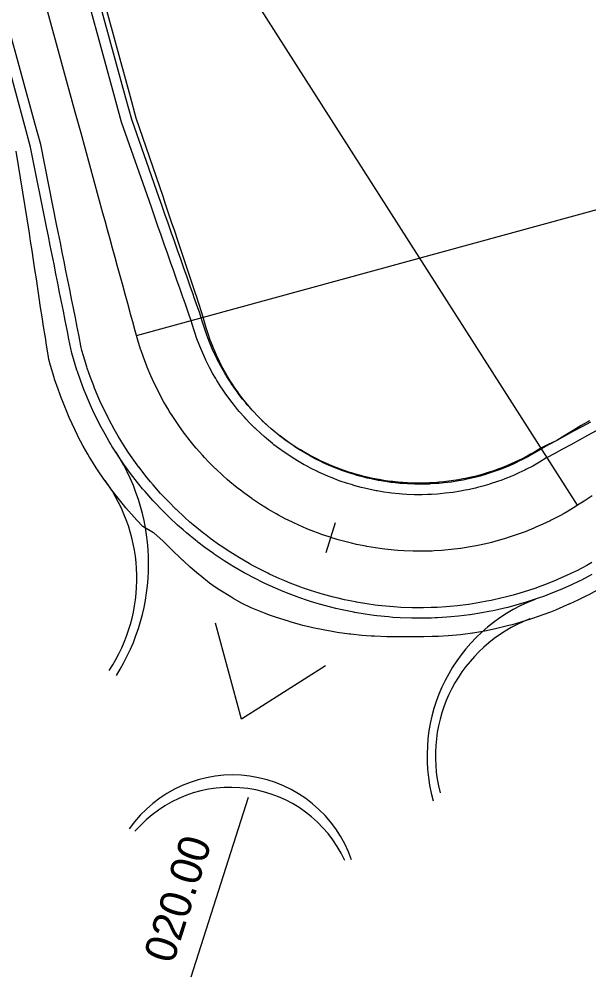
# Model space of a CAD drawing. Extents: x -550605 to -538780, y -1102367 to -1093705.
# Drawn here: x -547316.42 to -547289.25, y -1101242.46 to -1101196.75 of the extents above; entities that cross this region are included whole.
import ezdxf

# ---------------------------------------------------------------- set-up
doc = ezdxf.new("R2010")
doc.units = 0
for name, color, linetype in [('SIT - horní hrana zářezu', 7, 'Continuous'), ('SIT - hrany vozovky', 7, 'Continuous'), ('SIT - oblouky - hrany', 7, 'Continuous'), ('SIT - oblouky - koruna', 7, 'Continuous'), ('SIT - osa cesty', 7, 'Continuous'), ('SIT - paty násypů', 7, 'Continuous'), ('SIT - poloměry oblouků', 7, 'Continuous'), ('SIT - staničení hlavních bodů', 7, 'Continuous'), ('SIT - staničení po 30m', 7, 'Continuous')]:
    doc.layers.add(name, color=color, linetype=linetype)

msp = doc.modelspace()

# ---------------------------------------------------------------- linework, layer by layer
at = {"layer": 'SIT - horní hrana zářezu'}
msp.add_lwpolyline([(-547290.779, -1101216.854), (-547291.19, -1101217.054), (-547291.534, -1101217.223), (-547291.582, -1101217.253), (-547291.881, -1101217.432), (-547292.029, -1101217.516), (-547292.186, -1101217.602), (-547292.496, -1101217.762), (-547292.538, -1101217.783), (-547292.811, -1101217.913), (-547293.061, -1101218.023), (-547293.064, -1101218.024), (-547293.131, -1101218.053), (-547293.455, -1101218.182), (-547293.595, -1101218.235), (-547293.783, -1101218.301), (-547294.114, -1101218.41), (-547294.14, -1101218.418), (-547294.449, -1101218.508), (-547294.693, -1101218.572), (-547294.787, -1101218.595), (-547295.127, -1101218.671), (-547295.254, -1101218.697), (-547295.469, -1101218.736), (-547295.814, -1101218.791), (-547295.821, -1101218.792), (-547296.16, -1101218.834), (-547296.392, -1101218.857), (-547296.507, -1101218.866), (-547296.785, -1101218.884), (-547296.855, -1101218.887), (-547296.965, -1101218.891), (-547297.204, -1101218.897), (-547297.54, -1101218.896), (-547297.553, -1101218.896), (-547297.901, -1101218.883), (-547298.114, -1101218.87), (-547298.249, -1101218.86), (-547298.596, -1101218.825), (-547298.686, -1101218.814), (-547298.942, -1101218.779), (-547299.255, -1101218.728), (-547299.287, -1101218.722), (-547299.629, -1101218.655), (-547299.818, -1101218.612), (-547299.969, -1101218.576), (-547300.306, -1101218.486), (-547300.374, -1101218.467), (-547300.576, -1101218.406), (-547300.641, -1101218.386), (-547300.923, -1101218.292), (-547300.972, -1101218.275), (-547301.299, -1101218.153), (-547301.461, -1101218.089), (-547301.623, -1101218.021), (-547301.942, -1101217.879), (-547301.988, -1101217.858), (-547302.257, -1101217.727), (-547302.503, -1101217.599), (-547302.566, -1101217.564), (-547302.871, -1101217.392), (-547303.003, -1101217.313), (-547303.17, -1101217.21), (-547303.463, -1101217.019), (-547303.488, -1101217.001), (-547303.749, -1101216.816), (-547303.955, -1101216.661), (-547303.976, -1101216.645), (-547304.028, -1101216.605), (-547304.3, -1101216.384), (-547304.403, -1101216.297), (-547304.565, -1101216.156)], dxfattribs=at)
at = {"layer": 'SIT - hrany vozovky'}
for points in [[(-547288.909, -1101216.407), (-547289.309, -1101216.625), (-547289.709, -1101216.842), (-547290.109, -1101217.06), (-547290.509, -1101217.277), (-547290.909, -1101217.494), (-547291.245, -1101217.677), (-547291.295, -1101217.708), (-547291.608, -1101217.899), (-547291.763, -1101217.988), (-547291.927, -1101218.079), (-547292.252, -1101218.249), (-547292.296, -1101218.271), (-547292.583, -1101218.408), (-547292.844, -1101218.524), (-547292.848, -1101218.526), (-547292.918, -1101218.556), (-547293.258, -1101218.693), (-547293.405, -1101218.749), (-547293.602, -1101218.819), (-547293.95, -1101218.934), (-547293.977, -1101218.943), (-547294.302, -1101219.038), (-547294.559, -1101219.106), (-547294.657, -1101219.13), (-547295.014, -1101219.211), (-547295.148, -1101219.238), (-547295.375, -1101219.28), (-547295.737, -1101219.337), (-547295.744, -1101219.338), (-547296.1, -1101219.382), (-547296.344, -1101219.406), (-547296.466, -1101219.416), (-547296.758, -1101219.434), (-547296.831, -1101219.438), (-547296.947, -1101219.442), (-547297.198, -1101219.448), (-547297.551, -1101219.446), (-547297.565, -1101219.446), (-547297.931, -1101219.432), (-547298.155, -1101219.417), (-547298.297, -1101219.406), (-547298.661, -1101219.368), (-547298.756, -1101219.357), (-547299.025, -1101219.319), (-547299.353, -1101219.264), (-547299.386, -1101219.258), (-547299.745, -1101219.185), (-547299.944, -1101219.139), (-547300.102, -1101219.1), (-547300.456, -1101219.004), (-547300.527, -1101218.983), (-547300.739, -1101218.919), (-547300.807, -1101218.897), (-547301.102, -1101218.797), (-547301.153, -1101218.778), (-547301.496, -1101218.648), (-547301.665, -1101218.579), (-547301.835, -1101218.507), (-547302.168, -1101218.355), (-547302.216, -1101218.332), (-547302.497, -1101218.192), (-547302.754, -1101218.056), (-547302.82, -1101218.019), (-547303.137, -1101217.836), (-547303.275, -1101217.751), (-547303.448, -1101217.642), (-547303.753, -1101217.438), (-547303.78, -1101217.419), (-547304.051, -1101217.224), (-547304.266, -1101217.061), (-547304.288, -1101217.044), (-547304.342, -1101217.001), (-547304.626, -1101216.769), (-547304.733, -1101216.677), (-547304.901, -1101216.527), (-547305.169, -1101216.277), (-547305.178, -1101216.269), (-547305.429, -1101216.018), (-547305.6, -1101215.837), (-547305.68, -1101215.751), (-547305.922, -1101215.475), (-547305.999, -1101215.384), (-547306.155, -1101215.193), (-547306.374, -1101214.909), (-547306.379, -1101214.902), (-547306.593, -1101214.605), (-547306.722, -1101214.416), (-547306.798, -1101214.3), (-547306.958, -1101214.046), (-547306.993, -1101213.99), (-547307.044, -1101213.904), (-547307.177, -1101213.673), (-547307.337, -1101213.377), (-547307.351, -1101213.35), (-547307.514, -1101213.022), (-547307.602, -1101212.834), (-547307.667, -1101212.689), (-547307.809, -1101212.351), (-547307.838, -1101212.278), (-547307.94, -1101212.008), (-547308.044, -1101211.71), (-547308.059, -1101211.662), (-547308.168, -1101211.311), (-547308.219, -1101211.131), (-547308.292, -1101210.921), (-547308.443, -1101210.491), (-547308.568, -1101210.135), (-547308.594, -1101210.061), (-547308.744, -1101209.632), (-547308.895, -1101209.202), (-547309.045, -1101208.772), (-547309.196, -1101208.342), (-547309.347, -1101207.913), (-547309.497, -1101207.483), (-547309.648, -1101207.053), (-547309.798, -1101206.623), (-547309.949, -1101206.194), (-547310.099, -1101205.764), (-547310.225, -1101205.405), (-547311.534, -1101201.671), (-547311.812, -1101200.656), (-547313.118, -1101195.884)], [(-547289.177, -1101215.986), (-547289.578, -1101216.203), (-547289.978, -1101216.421), (-547290.378, -1101216.638), (-547290.778, -1101216.855), (-547291.178, -1101217.073), (-547291.513, -1101217.255), (-547291.561, -1101217.285), (-547291.861, -1101217.467), (-547292.008, -1101217.552), (-547292.166, -1101217.639), (-547292.477, -1101217.802), (-547292.519, -1101217.823), (-547292.792, -1101217.954), (-547293.042, -1101218.065), (-547293.045, -1101218.067), (-547293.113, -1101218.095), (-547293.438, -1101218.227), (-547293.578, -1101218.28), (-547293.767, -1101218.347), (-547294.099, -1101218.457), (-547294.125, -1101218.465), (-547294.435, -1101218.556), (-547294.681, -1101218.621), (-547294.775, -1101218.644), (-547295.116, -1101218.721), (-547295.244, -1101218.747), (-547295.461, -1101218.787), (-547295.807, -1101218.842), (-547295.814, -1101218.843), (-547296.154, -1101218.885), (-547296.387, -1101218.908), (-547296.503, -1101218.917), (-547296.783, -1101218.935), (-547296.853, -1101218.938), (-547296.964, -1101218.943), (-547297.203, -1101218.948), (-547297.541, -1101218.946), (-547297.554, -1101218.946), (-547297.904, -1101218.933), (-547298.118, -1101218.919), (-547298.253, -1101218.908), (-547298.602, -1101218.872), (-547298.692, -1101218.861), (-547298.949, -1101218.825), (-547299.263, -1101218.772), (-547299.295, -1101218.766), (-547299.638, -1101218.697), (-547299.828, -1101218.653), (-547299.979, -1101218.616), (-547300.317, -1101218.524), (-547300.385, -1101218.504), (-547300.587, -1101218.442), (-547300.652, -1101218.421), (-547300.934, -1101218.325), (-547300.984, -1101218.308), (-547301.311, -1101218.184), (-547301.473, -1101218.118), (-547301.635, -1101218.049), (-547301.954, -1101217.904), (-547302, -1101217.882), (-547302.268, -1101217.748), (-547302.513, -1101217.618), (-547302.577, -1101217.582), (-547302.88, -1101217.407), (-547303.012, -1101217.326), (-547303.177, -1101217.222), (-547303.469, -1101217.027), (-547303.494, -1101217.009), (-547303.753, -1101216.823), (-547303.959, -1101216.667), (-547303.98, -1101216.65), (-547304.031, -1101216.609), (-547304.302, -1101216.387), (-547304.405, -1101216.3), (-547304.566, -1101216.156), (-547304.822, -1101215.917), (-547304.83, -1101215.909), (-547305.07, -1101215.67), (-547305.234, -1101215.497), (-547305.31, -1101215.414), (-547305.541, -1101215.151), (-547305.615, -1101215.063), (-547305.764, -1101214.881), (-547305.973, -1101214.61), (-547305.978, -1101214.603), (-547306.183, -1101214.319), (-547306.306, -1101214.139), (-547306.379, -1101214.028), (-547306.532, -1101213.785), (-547306.565, -1101213.731), (-547306.613, -1101213.65), (-547306.741, -1101213.428), (-547306.894, -1101213.145), (-547306.907, -1101213.12), (-547307.063, -1101212.806), (-547307.147, -1101212.626), (-547307.209, -1101212.488), (-547307.345, -1101212.165), (-547307.373, -1101212.095), (-547307.47, -1101211.837), (-547307.569, -1101211.552), (-547307.584, -1101211.506), (-547307.688, -1101211.171), (-547307.736, -1101210.999), (-547307.81, -1101210.789), (-547307.961, -1101210.359), (-547308.085, -1101210.003), (-547308.111, -1101209.929), (-547308.262, -1101209.5), (-547308.412, -1101209.07), (-547308.563, -1101208.64), (-547308.714, -1101208.21), (-547308.864, -1101207.781), (-547309.015, -1101207.351), (-547309.165, -1101206.921), (-547309.316, -1101206.491), (-547309.467, -1101206.062), (-547309.617, -1101205.632), (-547309.743, -1101205.273), (-547311.051, -1101201.539), (-547311.329, -1101200.524), (-547312.635, -1101195.752)], [(-547289.107, -1101222.69), (-547289.351, -1101222.824), (-547289.831, -1101223.075), (-547289.896, -1101223.108), (-547290.319, -1101223.31), (-547290.706, -1101223.483), (-547290.711, -1101223.485), (-547290.815, -1101223.529), (-547291.317, -1101223.732), (-547291.535, -1101223.814), (-547291.826, -1101223.919), (-547292.34, -1101224.089), (-547292.38, -1101224.101), (-547292.86, -1101224.242), (-547293.24, -1101224.342), (-547293.384, -1101224.378), (-547293.913, -1101224.497), (-547294.111, -1101224.537), (-547294.445, -1101224.599), (-547294.98, -1101224.684), (-547294.991, -1101224.685), (-547295.518, -1101224.751), (-547295.878, -1101224.786), (-547296.057, -1101224.801), (-547296.489, -1101224.828), (-547296.598, -1101224.833), (-547296.769, -1101224.839), (-547297.14, -1101224.847), (-547297.662, -1101224.845), (-547297.682, -1101224.844), (-547298.223, -1101224.824), (-547298.554, -1101224.803), (-547298.764, -1101224.786), (-547299.303, -1101224.73), (-547299.442, -1101224.713), (-547299.84, -1101224.657), (-547300.324, -1101224.576), (-547300.374, -1101224.567), (-547300.905, -1101224.459), (-547301.198, -1101224.392), (-547301.432, -1101224.334), (-547301.955, -1101224.192), (-547302.06, -1101224.161), (-547302.373, -1101224.065), (-547302.473, -1101224.033), (-547302.909, -1101223.885), (-547302.986, -1101223.858), (-547303.492, -1101223.666), (-547303.742, -1101223.564), (-547303.992, -1101223.457), (-547304.485, -1101223.233), (-547304.557, -1101223.199), (-547304.971, -1101222.992), (-547305.351, -1101222.79), (-547305.449, -1101222.736), (-547305.917, -1101222.465), (-547306.122, -1101222.34), (-547306.377, -1101222.178), (-547306.828, -1101221.877), (-547306.867, -1101221.85), (-547307.268, -1101221.562), (-547307.586, -1101221.32), (-547307.618, -1101221.294), (-547307.698, -1101221.232), (-547308.117, -1101220.888), (-547308.275, -1101220.752), (-547308.525, -1101220.531), (-547308.92, -1101220.161), (-547308.933, -1101220.149), (-547309.304, -1101219.779), (-547309.558, -1101219.511), (-547309.675, -1101219.384), (-547310.033, -1101218.977), (-547310.147, -1101218.841), (-547310.378, -1101218.559), (-547310.7, -1101218.14), (-547310.708, -1101218.13), (-547311.025, -1101217.69), (-547311.215, -1101217.411), (-547311.327, -1101217.24), (-547311.564, -1101216.864), (-547311.615, -1101216.781), (-547311.69, -1101216.655), (-547311.888, -1101216.313), (-547312.124, -1101215.875), (-547312.145, -1101215.836), (-547312.386, -1101215.351), (-547312.516, -1101215.073), (-547312.612, -1101214.858), (-547312.822, -1101214.359), (-547312.865, -1101214.251), (-547313.015, -1101213.853), (-547313.168, -1101213.411), (-547313.192, -1101213.34), (-547313.352, -1101212.823), (-547313.427, -1101212.557), (-547313.471, -1101212.338), (-547313.56, -1101211.892), (-547313.634, -1101211.522), (-547313.649, -1101211.445), (-547313.739, -1101210.999), (-547313.828, -1101210.552), (-547313.917, -1101210.105), (-547314.006, -1101209.659), (-547314.095, -1101209.212), (-547314.185, -1101208.766), (-547314.274, -1101208.319), (-547314.363, -1101207.873), (-547314.452, -1101207.426), (-547314.542, -1101206.98), (-547314.616, -1101206.607), (-547315.392, -1101202.727), (-547315.67, -1101201.712), (-547316.976, -1101196.94)], [(-547289.112, -1101223.264), (-547289.607, -1101223.522), (-547289.674, -1101223.556), (-547290.109, -1101223.764), (-547290.508, -1101223.942), (-547290.513, -1101223.944), (-547290.62, -1101223.99), (-547291.137, -1101224.199), (-547291.361, -1101224.284), (-547291.661, -1101224.391), (-547292.191, -1101224.566), (-547292.232, -1101224.579), (-547292.726, -1101224.724), (-547293.117, -1101224.827), (-547293.267, -1101224.864), (-547293.811, -1101224.987), (-547294.015, -1101225.028), (-547294.359, -1101225.092), (-547294.91, -1101225.179), (-547294.922, -1101225.18), (-547295.464, -1101225.248), (-547295.835, -1101225.284), (-547296.02, -1101225.299), (-547296.464, -1101225.327), (-547296.577, -1101225.332), (-547296.753, -1101225.339), (-547297.135, -1101225.347), (-547297.672, -1101225.345), (-547297.693, -1101225.344), (-547298.25, -1101225.323), (-547298.591, -1101225.301), (-547298.807, -1101225.284), (-547299.362, -1101225.227), (-547299.506, -1101225.209), (-547299.915, -1101225.151), (-547300.414, -1101225.068), (-547300.465, -1101225.058), (-547301.012, -1101224.947), (-547301.314, -1101224.878), (-547301.555, -1101224.819), (-547302.094, -1101224.672), (-547302.202, -1101224.641), (-547302.524, -1101224.542), (-547302.627, -1101224.509), (-547303.076, -1101224.356), (-547303.155, -1101224.328), (-547303.677, -1101224.13), (-547303.934, -1101224.025), (-547304.192, -1101223.916), (-547304.7, -1101223.684), (-547304.773, -1101223.649), (-547305.2, -1101223.437), (-547305.591, -1101223.229), (-547305.692, -1101223.173), (-547306.175, -1101222.894), (-547306.385, -1101222.765), (-547306.649, -1101222.599), (-547307.112, -1101222.288), (-547307.153, -1101222.26), (-547307.566, -1101221.963), (-547307.893, -1101221.714), (-547307.927, -1101221.688), (-547308.009, -1101221.623), (-547308.44, -1101221.27), (-547308.603, -1101221.13), (-547308.86, -1101220.902), (-547309.268, -1101220.521), (-547309.281, -1101220.508), (-547309.663, -1101220.127), (-547309.924, -1101219.851), (-547310.045, -1101219.72), (-547310.414, -1101219.301), (-547310.531, -1101219.161), (-547310.769, -1101218.87), (-547311.101, -1101218.439), (-547311.109, -1101218.428), (-547311.435, -1101217.976), (-547311.631, -1101217.688), (-547311.747, -1101217.513), (-547311.991, -1101217.125), (-547312.043, -1101217.04), (-547312.121, -1101216.91), (-547312.324, -1101216.557), (-547312.568, -1101216.106), (-547312.589, -1101216.066), (-547312.837, -1101215.567), (-547312.971, -1101215.28), (-547313.07, -1101215.059), (-547313.286, -1101214.545), (-547313.33, -1101214.434), (-547313.485, -1101214.023), (-547313.643, -1101213.569), (-547313.667, -1101213.496), (-547313.832, -1101212.963), (-547313.909, -1101212.689), (-547313.953, -1101212.47), (-547314.042, -1101212.024), (-547314.116, -1101211.654), (-547314.132, -1101211.577), (-547314.221, -1101211.131), (-547314.31, -1101210.684), (-547314.399, -1101210.237), (-547314.489, -1101209.791), (-547314.578, -1101209.344), (-547314.667, -1101208.898), (-547314.756, -1101208.451), (-547314.846, -1101208.005), (-547314.935, -1101207.558), (-547315.024, -1101207.112), (-547315.098, -1101206.739), (-547315.874, -1101202.859), (-547316.152, -1101201.844), (-547317.458, -1101197.072)]]:
    msp.add_lwpolyline(points, dxfattribs=at)
at = {"layer": 'SIT - oblouky - hrany'}
for centre, radius, start, end in [((-547318.806, -1101223.442), 8, 326.6703, 35.729), ((-547289.568, -1101231.92), 7, 110.8447, 194.4829), ((-547306.339, -1101239.416), 6, 24.7664, 139.4064)]:
    msp.add_arc(centre, radius, start, end, dxfattribs=at)
at = {"layer": 'SIT - oblouky - koruna'}
for centre, radius, start, end in [((-547320.246, -1101222.755), 10, 327.7989, 32.2092), ((-547288.964, -1101231.924), 8, 110.8824, 195.4921), ((-547306.244, -1101238.826), 6, 18.9147, 145.1667)]:
    msp.add_arc(centre, radius, start, end, dxfattribs=at)
at = {"layer": 'SIT - osa cesty'}
msp.add_lwpolyline([(-547289.089, -1101219.504), (-547289.472, -1101219.749), (-547289.793, -1101219.953), (-547289.855, -1101219.993), (-547290.243, -1101220.228), (-547290.435, -1101220.339), (-547290.639, -1101220.452), (-547291.042, -1101220.662), (-547291.096, -1101220.689), (-547291.451, -1101220.859), (-547291.775, -1101221.004), (-547291.779, -1101221.005), (-547291.866, -1101221.043), (-547292.287, -1101221.213), (-547292.47, -1101221.282), (-547292.714, -1101221.369), (-547293.145, -1101221.512), (-547293.179, -1101221.522), (-547293.581, -1101221.64), (-547293.899, -1101221.724), (-547294.021, -1101221.754), (-547294.464, -1101221.854), (-547294.63, -1101221.888), (-547294.91, -1101221.939), (-547295.358, -1101222.01), (-547295.368, -1101222.012), (-547295.809, -1101222.067), (-547296.111, -1101222.096), (-547296.261, -1101222.108), (-547296.623, -1101222.131), (-547296.715, -1101222.135), (-547296.858, -1101222.141), (-547297.169, -1101222.148), (-547297.607, -1101222.145), (-547297.623, -1101222.145), (-547298.077, -1101222.128), (-547298.354, -1101222.11), (-547298.53, -1101222.096), (-547298.982, -1101222.049), (-547299.099, -1101222.035), (-547299.432, -1101221.988), (-547299.838, -1101221.92), (-547299.88, -1101221.912), (-547300.325, -1101221.822), (-547300.571, -1101221.766), (-547300.767, -1101221.717), (-547301.205, -1101221.598), (-547301.294, -1101221.572), (-547301.556, -1101221.492), (-547301.64, -1101221.465), (-547302.005, -1101221.341), (-547302.069, -1101221.318), (-547302.494, -1101221.157), (-547302.704, -1101221.072), (-547302.913, -1101220.982), (-547303.327, -1101220.794), (-547303.387, -1101220.765), (-547303.734, -1101220.592), (-547304.052, -1101220.423), (-547304.134, -1101220.378), (-547304.527, -1101220.15), (-547304.698, -1101220.046), (-547304.913, -1101219.91), (-547305.29, -1101219.658), (-547305.324, -1101219.635), (-547305.66, -1101219.393), (-547305.926, -1101219.19), (-547305.953, -1101219.169), (-547306.02, -1101219.116), (-547306.371, -1101218.828), (-547306.504, -1101218.715), (-547306.713, -1101218.529), (-547307.045, -1101218.219), (-547307.055, -1101218.209), (-547307.366, -1101217.898), (-547307.579, -1101217.674), (-547307.677, -1101217.567), (-547307.977, -1101217.226), (-547308.073, -1101217.112), (-547308.266, -1101216.876), (-547308.537, -1101216.525), (-547308.544, -1101216.516), (-547308.809, -1101216.147), (-547308.969, -1101215.913), (-547309.063, -1101215.77), (-547309.261, -1101215.455), (-547309.304, -1101215.385), (-547309.367, -1101215.28), (-547309.532, -1101214.993), (-547309.731, -1101214.626), (-547309.748, -1101214.593), (-547309.95, -1101214.187), (-547310.059, -1101213.953), (-547310.14, -1101213.774), (-547310.315, -1101213.355), (-547310.351, -1101213.264), (-547310.477, -1101212.93), (-547310.606, -1101212.561), (-547310.626, -1101212.501), (-547310.76, -1101212.067), (-547310.823, -1101211.844), (-547310.882, -1101211.629), (-547311.001, -1101211.191), (-547311.101, -1101210.829), (-547311.121, -1101210.753), (-547311.241, -1101210.315), (-547311.361, -1101209.877), (-547311.481, -1101209.439), (-547311.601, -1101209.001), (-547311.721, -1101208.563), (-547311.841, -1101208.124), (-547311.961, -1101207.686), (-547312.081, -1101207.248), (-547312.201, -1101206.81), (-547312.321, -1101206.372), (-547312.421, -1101206.006), (-547313.463, -1101202.199), (-547313.741, -1101201.184), (-547315.047, -1101196.412)], dxfattribs=at)
at = {"layer": 'SIT - paty násypů'}
for points in [[(-547304.565, -1101216.156), (-547304.821, -1101215.916), (-547304.829, -1101215.908), (-547305.066, -1101215.666), (-547305.228, -1101215.492), (-547305.303, -1101215.408), (-547305.532, -1101215.143), (-547305.604, -1101215.054), (-547305.751, -1101214.87), (-547305.955, -1101214.597), (-547305.96, -1101214.59), (-547306.161, -1101214.304), (-547306.281, -1101214.122), (-547306.351, -1101214.01), (-547306.5, -1101213.766), (-547306.531, -1101213.711), (-547306.579, -1101213.629), (-547306.702, -1101213.407), (-547306.849, -1101213.122), (-547306.861, -1101213.096), (-547307.011, -1101212.781), (-547307.09, -1101212.601), (-547307.149, -1101212.461), (-547307.276, -1101212.137), (-547307.303, -1101212.067), (-547307.396, -1101211.81), (-547307.49, -1101211.526), (-547307.505, -1101211.48), (-547307.602, -1101211.146), (-547307.648, -1101210.975), (-547307.712, -1101210.762), (-547307.847, -1101210.328), (-547307.966, -1101209.971), (-547307.991, -1101209.896), (-547308.135, -1101209.465), (-547308.279, -1101209.033), (-547308.424, -1101208.602), (-547308.568, -1101208.17), (-547308.712, -1101207.739), (-547308.857, -1101207.308), (-547309.001, -1101206.876), (-547309.146, -1101206.445), (-547309.29, -1101206.013), (-547309.435, -1101205.582), (-547309.556, -1101205.222), (-547310.831, -1101201.479), (-547311.107, -1101200.463), (-547312.405, -1101195.689)], [(-547288.743, -1101223.943), (-547289.257, -1101224.22), (-547289.326, -1101224.256), (-547289.778, -1101224.481), (-547290.192, -1101224.674), (-547290.197, -1101224.676), (-547290.309, -1101224.726), (-547290.846, -1101224.954), (-547291.079, -1101225.047), (-547291.391, -1101225.166), (-547291.943, -1101225.361), (-547291.986, -1101225.375), (-547292.501, -1101225.538), (-547292.909, -1101225.656), (-547293.064, -1101225.698), (-547293.633, -1101225.839), (-547293.847, -1101225.885), (-547294.208, -1101225.956), (-547294.786, -1101226.056), (-547294.798, -1101226.058), (-547295.368, -1101226.129), (-547295.759, -1101226.166), (-547295.953, -1101226.182), (-547296.42, -1101226.21), (-547296.539, -1101226.216), (-547296.724, -1101226.223), (-547297.125, -1101226.231), (-547297.69, -1101226.227), (-547297.712, -1101226.227), (-547298.299, -1101226.224), (-547298.659, -1101226.226), (-547298.889, -1101226.224), (-547299.479, -1101226.203), (-547299.632, -1101226.195), (-547300.069, -1101226.163), (-547300.604, -1101226.108), (-547300.659, -1101226.102), (-547301.248, -1101226.02), (-547301.574, -1101225.966), (-547301.835, -1101225.919), (-547302.418, -1101225.796), (-547302.536, -1101225.769), (-547302.886, -1101225.683), (-547302.999, -1101225.654), (-547303.489, -1101225.517), (-547303.575, -1101225.491), (-547304.146, -1101225.309), (-547304.428, -1101225.21), (-547304.711, -1101225.106), (-547305.27, -1101224.883), (-547305.35, -1101224.849), (-547305.808, -1101224.617), (-547306.224, -1101224.383), (-547306.331, -1101224.32), (-547306.842, -1101224.005), (-547307.064, -1101223.861), (-547307.34, -1101223.67), (-547307.807, -1101223.291), (-547307.848, -1101223.257), (-547308.261, -1101222.9), (-547308.587, -1101222.605), (-547308.621, -1101222.574), (-547308.702, -1101222.498), (-547309.13, -1101222.084), (-547309.291, -1101221.922), (-547309.545, -1101221.659), (-547309.996, -1101221.275), (-547310.013, -1101221.265), (-547310.524, -1101220.963), (-547310.803, -1101220.667), (-547310.931, -1101220.526), (-547311.324, -1101220.077), (-547311.45, -1101219.927), (-547311.703, -1101219.615), (-547312.057, -1101219.154), (-547312.066, -1101219.142), (-547312.414, -1101218.657), (-547312.624, -1101218.35), (-547312.747, -1101218.162), (-547313.008, -1101217.748), (-547313.064, -1101217.656), (-547313.147, -1101217.517), (-547313.36, -1101217.138), (-547313.613, -1101216.652), (-547313.635, -1101216.609), (-547313.893, -1101216.071), (-547314.032, -1101215.763), (-547314.134, -1101215.526), (-547314.357, -1101214.974), (-547314.403, -1101214.855), (-547314.563, -1101214.415), (-547314.726, -1101213.929), (-547314.751, -1101213.851), (-547314.921, -1101213.28), (-547315.001, -1101212.988), (-547315.036, -1101212.767), (-547315.109, -1101212.315), (-547315.169, -1101211.942), (-547315.181, -1101211.864), (-547315.255, -1101211.413), (-547315.327, -1101210.962), (-547315.394, -1101210.51), (-547315.461, -1101210.057), (-547315.528, -1101209.605), (-547315.596, -1101209.152), (-547315.665, -1101208.7), (-547315.733, -1101208.248), (-547315.803, -1101207.796), (-547315.873, -1101207.344), (-547315.931, -1101206.967), (-547316.554, -1101203.045)], [(-547289.221, -1101215.918), (-547289.613, -1101216.147), (-547290.004, -1101216.38), (-547290.391, -1101216.617), (-547290.779, -1101216.854)]]:
    msp.add_lwpolyline(points, dxfattribs=at)
at = {"layer": 'SIT - poloměry oblouků'}
msp.add_lwpolyline([(-547301.805, -1101227.611), (-547305.809, -1101230.164), (-547307.062, -1101225.584)], dxfattribs=at)
at = {"layer": 'SIT - staničení hlavních bodů'}
for points in [[(-547289.793, -1101219.953), (-547313.985, -1101182.009)], [(-547310.823, -1101211.844), (-547267.419, -1101199.965)]]:
    msp.add_lwpolyline(points, dxfattribs=at)
at = {"layer": 'SIT - staničení po 30m'}
for points in [[(-547301.783, -1101222.207), (-547301.329, -1101220.777)], [(-547308.213, -1101242.461), (-547305.489, -1101233.883)]]:
    msp.add_lwpolyline(points, dxfattribs=at)

# ---------------------------------------------------------------- texts
msp.add_text('020.00', height=1.5, rotation=72.3866, dxfattribs=at).set_placement((-547309.079, -1101241.883))

doc.saveas('drawing.dxf')
